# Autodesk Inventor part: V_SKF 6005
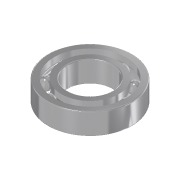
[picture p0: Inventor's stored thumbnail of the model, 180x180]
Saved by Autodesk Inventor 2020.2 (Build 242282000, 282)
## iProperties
Manager: www.cadconsulting.pl
Company: Fabian Stasiak CAD Consulting
+MSCProtocol1+ProtocolID: P00060228133459765
+MSCProtocol2+Protocol: P00060228133459765<@PID>[Version]<@EL>Version=2.2<@EL>[Files]<@EL>DataFile=SpiData|n024630a<@EL>[Synchronize]<@EL>ChangedVars=<@EL>[Calc]<@EL>DDmin=<@EL>DDmax=<
Shininess: 20.0
Length Units: 11269
Angle Units: 11279
Time Units: 11290
Mass Units: 11283
Length Display Precision: 3
Angle Display Precision: 2
Created: 2001-01
Part Number: V_SKF 6005
Material: Stal
Document SubType Name: Modeling
Description: Łożysko SKF 6005
Stock Number: SKF 6005
Project: Przekładnia X51
Designer: F.Stasiak
Density: 7.85 g/cm^3
Appearance: Chrom
Density: 7.86
Volumn: 47.63899704516156
Area: 199.2492810037185
PropertySet Name: Model Information
Control State: 0
Master: False
Checked Out: False
BOM1: Łożysko
BOM2: SKF 6005
Author: F.Stasiak
Subject: Zbiór ćwiczeń. Autodesk Inventor 2020. Kurs podstawowy
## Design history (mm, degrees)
node "Sketch1"
node "WorkPoint1"
sketch "Sketch2"
  geometry: L1 (12.5, 12)-(23.5, 12); L2 (12.5, 0)-(12.5, 12); L3 (23.5, 0)-(12.5, 0); L4 (23.5, 12)-(23.5, 0); L5 (0, 0)-(0, 20); L6 (0, 0)-(0, 20); L7 (-3.6, 0)-(46.8, 0) reference
  constraints: 12 end point, 3 vertical, 2 horizontal, 1 collinear, 1 other
  dimensions: "d1" = 25 diameter of L1.start L5 (= prf_d); "d3" = 47 diameter of L1.end L5 (= prf_dd); "d5" = 12 distance of L2.start L1.start (= msp_mdtd2)
revolve "RevolutionFull1" sketch "Sketch2" stored, may be unused: angle "d6" = 360 deg
node "WorkAxis1"
node "WorkPlane3"
sketch "Sketch3"
  geometry: L1 (19.98, 12)-(19.98, 8.64); L2 (16.02, 12)-(19.98, 12); L3 (16.02, 8.64)-(16.02, 12); L4 (16.02, 0)-(16.02, 3.36); L5 (19.98, 0)-(16.02, 0); L6 (19.98, 3.36)-(19.98, 0); L7 (23.5, 0)-(-23.5, 0) reference; L8 (23.5, 12)-(-23.5, 12) reference; L9 (0, -42.29)-(0, 61.29); L10 (0, 92.365)-(0, -52.649) reference; A1 r 3.3 centre (18, 6) between (19.98, 3.36) and (19.98, 8.64); A2 r 3.3 centre (18, 6) between (16.02, 8.64) and (16.02, 3.36)
  constraints: 14 end point, 4 collinear, 4 point on circle, 4 vertical, 2 centre point, 2 concentric, 2 horizontal, 2 point on line
  dimensions: "d9" = 6.6 diameter of A1 (= msp_mdtd6); "d21" = 16.02 distance between parallel lines of L9 L4 (= 0.5 x msp_d1); "d22" = 18 distance from line of L9 A1.centre (= 0.5 x msp_ds); "d23" = 19.98 distance between parallel lines of L9 L6 (= 0.5 x msp_dd1)
revolve "RevolutionFull2" sketch "Sketch3" stored, may be unused: angle "d10" = 360 deg
node "WorkPlane4"
node "Sketch4"
node "WorkPoint2"
revolve "RevolutionFull3" stored, may be unused: angle "d16" = 360 deg
pattern_circular "PolarAray1" dims "d17" = 85.81818 (= msp_pocet), angle "d19" = 360 deg
fillet "Fillet1" dims "d20" = 0.6 (= prf_r)
node "Bryła1"
node "Korpusy bryłowe"
node "Korpusy powierzchniowe"
sketch "Sketch5"
  geometry: L1 (18, 2.7)-(18, 9.3); L2 (19.98, 0)-(-19.98, 0) reference; L3 (18, 2.7)-(18, 9.3); A1 r 3.3 centre (18, 6) between (18, 2.7) and (18, 9.3); A2 r 3.3 centre (18, 6) between (19.98, 3.36) and (19.98, 8.64) reference
  constraints: 4 end point, 2 point on circle, 1 centre point, 1 concentric, 1 vertical
  dimensions: "d13" = 0 horizontal distance of A1.centre L1.start; "d15" = 6.6001 diameter of A1 (computed from msp_mdtd6)
other parameters: "prf_d" = 25 [user parameter; used in 3 equation terms], "prf_dd" = 47 [user parameter; used in 3 equation terms], "prf_b" = 12 [user parameter; used in 1 equation term], "prf_r" = 0.6 [user parameter; used in 1 equation term], "msp_ds" = 36 (= 0.5 x prf_d + 0.5 x prf_dd) [user parameter; used in 5 equation terms], "msp_d0" = 6.6 (= -0.3 x prf_d + 0.3 x prf_dd) [user parameter; used in 4 equation terms], "msp_d1" = 32.04 (= msp_ds - 0.6 x msp_d0) [user parameter; used in 1 equation term], "msp_dd1" = 39.96 (= msp_ds + 0.6 x msp_d0) [user parameter; used in 1 equation term], "msp_pom" = 54 (= 1.5 x msp_ds) [user parameter; used in 1 equation term], "msp_mdtd2" = 12 (= prf_b) [user parameter; used in 3 equation terms], "msp_mdtd4" = 36 (= msp_ds) [user parameter], "msp_mdtd6" = 6.6 (= msp_d0) [user parameter; used in 2 equation terms], "msp_mdtd7" = 6 (= 0.5 x msp_mdtd2) [user parameter], "msp_pocet" = 85.81818 (computed from msp_d0, msp_pom) [user parameter; used in 1 equation term], "d2" = 72 (derived), "d4" = 19 (derived), "d7" = 0, "d8" = 15.6 (derived), "d11" = -12 (computed from msp_mdtd2), "d12" = 0 (derived), "d14" = 15.6001 (derived), "d25" = 0
